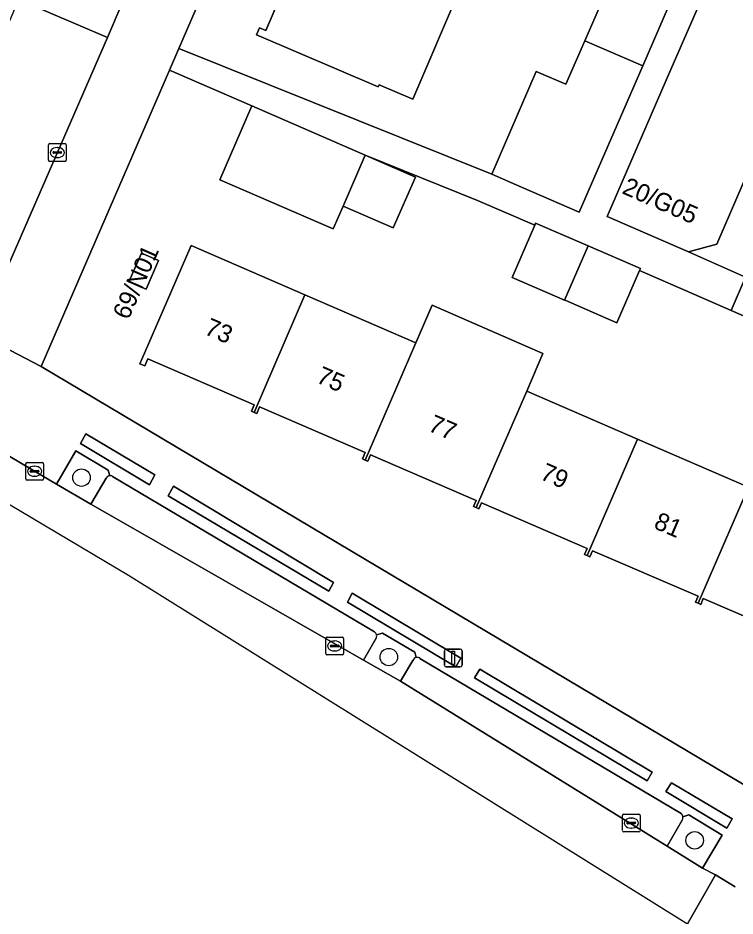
# Model space of a CAD drawing. Extents: x 162803 to 163818, y 381639 to 382475.
# Drawn here: x 163394.5 to 163434.7, y 381804.9 to 381855.2 of the extents above; entities that cross this region are included whole.
import ezdxf

# ---------------------------------------------------------------- set-up
doc = ezdxf.new("R2010")
doc.units = 0
for name, color, linetype in [('IMGEO_Berm_groen', 7, 'Continuous'), ('IMGEO_Boom', 7, 'Continuous'), ('IMGEO_Erf', 7, 'Continuous'), ('IMGEO_Groenvoorziening', 7, 'Continuous'), ('IMGEO_Kolk', 7, 'Continuous'), ('IMGEO_Lichtmast', 7, 'Continuous'), ('IMGEO_Pand', 7, 'Continuous'), ('IMGEO_Pand_nummerreeks', 7, 'Continuous'), ('IMGEO_Parkeervlak_open', 7, 'Continuous'), ('IMGEO_Rijbaan_lokaal_gesloten', 7, 'Continuous'), ('IMGEO_Rijbaan_lokaal_open', 7, 'Continuous'), ('IMGEO_Voetpad_open', 7, 'Continuous')]:
    doc.layers.add(name, color=color, linetype=linetype)

msp = doc.modelspace()

# ---------------------------------------------------------------- linework, layer by layer
at = {"layer": 'IMGEO_Berm_groen'}
for points in [[(163399.544, 381854.142), (163394.559, 381856.298), (163394.49, 381856.13), (163392.212, 381850.821), (163391.661, 381850.394), (163389.556, 381850), (163388.971, 381849.512), (163387.609, 381847.192)], [(163389.452, 381839.39), (163392.292, 381837.534), (163399.544, 381854.142)]]:
    msp.add_lwpolyline(points, dxfattribs=at)
at = {"layer": 'IMGEO_Boom'}
for centre in [(163398.089, 381829.482), (163415.32, 381819.425), (163432.47, 381809.155)]:
    msp.add_circle(centre, 0.489, dxfattribs=at)
at = {"layer": 'IMGEO_Erf'}
for points in [[(163433.958, 381923.664), (163403.547, 381853.528), (163421.091, 381846.477), (163423.59, 381852.241), (163425.254, 381851.519), (163426.307, 381853.949), (163428.657, 381859.374)], [(163419.342, 381856.95), (163416.671, 381850.68), (163414.775, 381851.488), (163414.731, 381851.385), (163407.904, 381854.294), (163408.07, 381854.678), (163408.419, 381854.527), (163410.948, 381860.393)], [(163436.198, 381838.123), (163434.517, 381838.854), (163432.723, 381839.632), (163429.378, 381841.081), (163428.109, 381838.155), (163425.245, 381839.398), (163425.173, 381839.429), (163422.236, 381840.702), (163423.504, 381843.626), (163420.299, 381845.015), (163413.989, 381847.548), (163416.807, 381846.326), (163415.568, 381843.47), (163412.751, 381844.692), (163412.199, 381843.419), (163405.84, 381846.176), (163407.63, 381850.305), (163403.019, 381852.311), (163395.819, 381835.705), (163436.629, 381811.45)], [(163438.975, 381820.104), (163432.952, 381822.703), (163432.812, 381822.379), (163432.665, 381822.443), (163432.518, 381822.507), (163432.658, 381822.83), (163426.732, 381825.387), (163426.587, 381825.052), (163426.44, 381825.116), (163426.293, 381825.18), (163426.438, 381825.514), (163420.511, 381828.071), (163420.368, 381827.74), (163420.221, 381827.804), (163420.074, 381827.868), (163420.217, 381828.198), (163414.29, 381830.755), (163414.137, 381830.401), (163413.99, 381830.465), (163413.843, 381830.529), (163413.996, 381830.882), (163408.07, 381833.439), (163407.912, 381833.075), (163407.765, 381833.138), (163407.618, 381833.201), (163407.776, 381833.566), (163401.81, 381836.14), (163401.638, 381835.742), (163401.368, 381835.859), (163401.495, 381836.153), (163402.857, 381839.295), (163404.241, 381842.487), (163410.618, 381839.723), (163416.834, 381837.028), (163417.748, 381839.137), (163423.964, 381836.441), (163423.05, 381834.333), (163429.266, 381831.638), (163435.482, 381828.943)]]:
    msp.add_lwpolyline(points, dxfattribs=at)
msp.add_lwpolyline([(163401.711, 381840.043), (163400.747, 381840.461), (163401.443, 381842.066), (163402.407, 381841.648)], close=True, dxfattribs=at)
at = {"layer": 'IMGEO_Groenvoorziening'}
for points in [[(163435.32, 381840.713), (163434.517, 381838.854), (163436.198, 381838.123), (163436.268, 381838.286), (163439.015, 381837.095), (163441.782, 381835.896), (163441.712, 381835.735), (163448.992, 381832.592), (163449.775, 381834.399), (163449.934, 381834.765), (163435.46, 381841.037)], [(163398.324, 381831.926), (163398.029, 381831.389), (163401.897, 381829.068), (163402.208, 381829.635)], [(163403.238, 381828.994), (163402.941, 381828.464), (163411.956, 381823.122), (163412.22, 381823.608)], [(163413.257, 381823.001), (163412.996, 381822.5), (163419.074, 381818.874), (163419.357, 381819.373)], [(163420.415, 381818.757), (163420.12, 381818.266), (163429.799, 381812.496), (163430.078, 381812.97)], [(163431.168, 381812.385), (163430.856, 381811.886), (163434.272, 381809.838), (163434.575, 381810.357)]]:
    msp.add_lwpolyline(points, close=True, dxfattribs=at)
for points in [[(163399.682, 381829.584), (163399.575, 381829.895), (163397.779, 381830.986), (163396.691, 381829.107)], [(163396.691, 381829.107), (163398.609, 381827.994), (163399.48, 381829.459)], [(163414.615, 381820.483), (163413.902, 381819.257), (163415.975, 381818.069), (163416.665, 381819.235)], [(163416.86, 381819.395), (163416.785, 381819.695), (163414.959, 381820.767), (163414.634, 381820.669)], [(163431.763, 381810.278), (163430.921, 381808.822), (163432.917, 381807.601), (163434.015, 381809.443), (163432.139, 381810.578), (163431.812, 381810.474)]]:
    msp.add_lwpolyline(points, dxfattribs=at)
for centre, radius, start, end in [((163399.696, 381829.335), 0.249, 93.3052, 150.1942), ((163414.332, 381820.606), 0.308, 336.5018, 11.8331), ((163416.908, 381819.137), 0.262, 100.6135, 158.1252), ((163431.538, 381810.438), 0.276, 324.4834, 7.4441)]:
    msp.add_arc(centre, radius, start, end, dxfattribs=at)
at = {"layer": 'IMGEO_Kolk'}
for p, q in [((163396.23, 381847.27), (163396.23, 381848.122)), ((163396.305, 381848.196), (163397.157, 381848.196)), ((163397.231, 381848.122), (163397.231, 381847.27)), ((163396.489, 381847.69), (163396.489, 381847.702)), ((163396.927, 381847.653), (163396.529, 381847.653)), ((163396.532, 381847.739), (163396.93, 381847.739)), ((163396.718, 381847.976), (163396.743, 381847.976)), ((163396.973, 381847.702), (163396.973, 381847.69)), ((163397.157, 381847.196), (163396.305, 381847.196)), ((163396.741, 381847.416), (163396.716, 381847.416)), ((163394.958, 381829.41), (163394.958, 381830.262)), ((163395.033, 381830.336), (163395.885, 381830.336)), ((163395.26, 381829.879), (163395.658, 381829.879)), ((163395.446, 381830.116), (163395.471, 381830.116)), ((163395.959, 381830.262), (163395.959, 381829.41)), ((163395.217, 381829.83), (163395.217, 381829.842)), ((163395.655, 381829.793), (163395.257, 381829.793)), ((163395.469, 381829.556), (163395.444, 381829.556)), ((163395.701, 381829.842), (163395.701, 381829.83)), ((163395.885, 381829.336), (163395.033, 381829.336)), ((163411.785, 381819.621), (163411.785, 381820.473)), ((163411.86, 381820.547), (163412.712, 381820.547)), ((163412.273, 381820.327), (163412.298, 381820.327)), ((163412.786, 381820.473), (163412.786, 381819.621)), ((163412.044, 381820.041), (163412.044, 381820.053)), ((163412.482, 381820.004), (163412.084, 381820.004)), ((163412.087, 381820.09), (163412.485, 381820.09)), ((163412.528, 381820.053), (163412.528, 381820.041)), ((163412.712, 381819.547), (163411.86, 381819.547)), ((163412.296, 381819.767), (163412.271, 381819.767)), ((163428.415, 381809.699), (163428.415, 381810.551)), ((163428.49, 381810.625), (163429.342, 381810.625)), ((163428.903, 381810.405), (163428.928, 381810.405)), ((163429.416, 381810.551), (163429.416, 381809.699)), ((163428.674, 381810.119), (163428.674, 381810.131)), ((163429.112, 381810.082), (163428.714, 381810.082)), ((163428.717, 381810.168), (163429.115, 381810.168)), ((163428.926, 381809.845), (163428.901, 381809.845)), ((163429.158, 381810.131), (163429.158, 381810.119)), ((163429.342, 381809.625), (163428.49, 381809.625))]:
    msp.add_line(p, q, dxfattribs=at)
for points in [[(163396.23, 381847.27), (163396.23, 381848.122)], [(163396.305, 381848.196), (163397.157, 381848.196)], [(163397.231, 381848.122), (163397.231, 381847.27)], [(163397.157, 381847.196), (163396.305, 381847.196)], [(163394.958, 381829.41), (163394.958, 381830.262)], [(163395.033, 381830.336), (163395.885, 381830.336)], [(163395.959, 381830.262), (163395.959, 381829.41)], [(163395.885, 381829.336), (163395.033, 381829.336)], [(163411.785, 381819.621), (163411.785, 381820.473)], [(163411.86, 381820.547), (163412.712, 381820.547)], [(163412.786, 381820.473), (163412.786, 381819.621)], [(163412.712, 381819.547), (163411.86, 381819.547)], [(163428.415, 381809.699), (163428.415, 381810.551)], [(163428.49, 381810.625), (163429.342, 381810.625)], [(163429.416, 381810.551), (163429.416, 381809.699)], [(163429.342, 381809.625), (163428.49, 381809.625)]]:
    msp.add_lwpolyline(points, dxfattribs=at)
for centre, radius, start, end in [((163396.307, 381848.12), 0.0765, 91.552, 178.448), ((163396.307, 381848.12), 0.0765, 91.552, 178.448), ((163397.155, 381848.12), 0.0765, 1.552, 88.448), ((163397.155, 381848.12), 0.0765, 1.552, 88.448), ((163396.529, 381847.699), 0.0403, 85.8775, 175.7526), ((163396.526, 381847.689), 0.0366, 178.938, 274.7102), ((163396.93, 381847.696), 0.043, 264.8664, 352.4533), ((163396.934, 381847.701), 0.0386, 1.7309, 96.639), ((163396.307, 381847.272), 0.0765, 181.552, 268.448), ((163396.307, 381847.272), 0.0765, 181.552, 268.448), ((163397.155, 381847.272), 0.0765, 271.552, 358.448), ((163397.155, 381847.272), 0.0765, 271.552, 358.448), ((163395.035, 381830.26), 0.0765, 91.552, 178.448), ((163395.035, 381830.26), 0.0765, 91.552, 178.448), ((163395.257, 381829.839), 0.0403, 85.8775, 175.7526), ((163395.662, 381829.841), 0.0386, 1.7309, 96.639), ((163395.883, 381830.26), 0.0765, 1.552, 88.448), ((163395.883, 381830.26), 0.0765, 1.552, 88.448), ((163395.035, 381829.412), 0.0765, 181.552, 268.448), ((163395.035, 381829.412), 0.0765, 181.552, 268.448), ((163395.254, 381829.829), 0.0366, 178.938, 274.7102), ((163395.658, 381829.836), 0.043, 264.8664, 352.4533), ((163395.883, 381829.412), 0.0765, 271.552, 358.448), ((163395.883, 381829.412), 0.0765, 271.552, 358.448), ((163411.862, 381820.471), 0.0765, 91.552, 178.448), ((163411.862, 381820.471), 0.0765, 91.552, 178.448), ((163412.71, 381820.471), 0.0765, 1.552, 88.448), ((163412.71, 381820.471), 0.0765, 1.552, 88.448), ((163412.084, 381820.05), 0.0403, 85.8775, 175.7526), ((163412.081, 381820.04), 0.0366, 178.938, 274.7102), ((163412.485, 381820.047), 0.043, 264.8664, 352.4533), ((163412.489, 381820.052), 0.0386, 1.7309, 96.639), ((163411.862, 381819.623), 0.0765, 181.552, 268.448), ((163411.862, 381819.623), 0.0765, 181.552, 268.448), ((163412.71, 381819.623), 0.0765, 271.552, 358.448), ((163412.71, 381819.623), 0.0765, 271.552, 358.448), ((163428.492, 381810.549), 0.0765, 91.552, 178.448), ((163428.492, 381810.549), 0.0765, 91.552, 178.448), ((163429.34, 381810.549), 0.0765, 1.552, 88.448), ((163429.34, 381810.549), 0.0765, 1.552, 88.448), ((163428.714, 381810.128), 0.0403, 85.8775, 175.7526), ((163428.711, 381810.118), 0.0366, 178.938, 274.7102), ((163429.115, 381810.125), 0.043, 264.8664, 352.4533), ((163429.119, 381810.13), 0.0386, 1.7309, 96.639), ((163428.492, 381809.701), 0.0765, 181.552, 268.448), ((163428.492, 381809.701), 0.0765, 181.552, 268.448), ((163429.34, 381809.701), 0.0765, 271.552, 358.448), ((163429.34, 381809.701), 0.0765, 271.552, 358.448)]:
    msp.add_arc(centre, radius, start, end, dxfattribs=at)
for centre, major_axis, ratio, start_param, end_param in [((163396.717, 381847.696), (-0.387, 0.002), 0.722429, 4.712389, 7.853982), ((163396.742, 381847.696), (-0.39, 0.002), 0.717154, 1.570796, 4.712389), ((163395.445, 381829.836), (-0.387, 0.002), 0.722429, 4.712389, 7.853982), ((163395.47, 381829.836), (-0.39, 0.002), 0.717154, 1.570796, 4.712389), ((163412.272, 381820.047), (-0.387, 0.002), 0.722429, 4.712389, 7.853982), ((163412.297, 381820.047), (-0.39, 0.002), 0.717154, 1.570796, 4.712389), ((163428.902, 381810.125), (-0.387, 0.002), 0.722429, 4.712389, 7.853982), ((163428.927, 381810.125), (-0.39, 0.002), 0.717154, 1.570796, 4.712389)]:
    msp.add_ellipse(centre, major_axis=major_axis, ratio=ratio, start_param=start_param, end_param=end_param, dxfattribs=at)
at = {"layer": 'IMGEO_Lichtmast'}
for p, q in [((163418.537, 381819.876), (163419.327, 381819.876)), ((163419.327, 381819.876), (163418.537, 381819.876)), ((163418.437, 381818.976), (163418.437, 381819.776)), ((163418.437, 381819.776), (163418.437, 381818.976)), ((163419.427, 381819.776), (163419.427, 381818.976)), ((163419.427, 381818.976), (163419.427, 381819.776)), ((163419.327, 381818.876), (163418.537, 381818.876)), ((163418.537, 381818.876), (163419.327, 381818.876))]:
    msp.add_line(p, q, dxfattribs=at)
msp.add_lwpolyline([(163418.857, 381819.751), (163419.007, 381819.751), (163419.007, 381819.001), (163418.857, 381819.001), (163418.857, 381819.751)], dxfattribs=at)
for centre, start, end in [((163418.537, 381819.776), 90, 180), ((163418.537, 381819.776), 90, 180), ((163419.327, 381819.776), 0, 90), ((163419.327, 381819.776), 360, 90), ((163418.537, 381818.976), 180, 270), ((163418.537, 381818.976), 180, 270), ((163419.327, 381818.976), 270, 0), ((163419.327, 381818.976), 270, 0)]:
    msp.add_arc(centre, 0.1, start, end, dxfattribs=at)
at = {"layer": 'IMGEO_Pand'}
for points in [[(163419.342, 381856.95), (163410.697, 381860.675), (163410.634, 381860.528), (163410.948, 381860.393), (163408.419, 381854.527), (163408.07, 381854.678), (163407.904, 381854.294), (163414.731, 381851.385), (163414.775, 381851.488), (163416.671, 381850.68)], [(163431.903, 381857.968), (163431.665, 381858.071), (163428.657, 381859.374), (163426.307, 381853.949), (163429.555, 381852.549)], [(163438.987, 381854.752), (163436.121, 381855.995), (163433.255, 381857.237), (163430.874, 381851.744), (163427.569, 381844.119), (163432.128, 381842.14), (163433.704, 381842.563), (163436.605, 381849.259)], [(163429.555, 381852.549), (163426.307, 381853.949), (163425.254, 381851.519), (163423.59, 381852.241), (163421.091, 381846.477), (163422.756, 381845.755), (163426.001, 381844.348)], [(163413.989, 381847.548), (163407.63, 381850.305), (163405.84, 381846.176), (163412.199, 381843.419), (163412.751, 381844.692)], [(163413.989, 381847.548), (163412.751, 381844.692), (163415.568, 381843.47), (163416.807, 381846.326)], [(163426.491, 381842.468), (163423.554, 381843.742), (163423.504, 381843.626), (163422.236, 381840.702), (163425.173, 381839.429)], [(163410.618, 381839.723), (163404.241, 381842.487), (163402.857, 381839.295), (163401.495, 381836.153), (163401.368, 381835.859), (163401.638, 381835.742), (163401.81, 381836.14), (163407.776, 381833.566), (163407.618, 381833.201), (163407.765, 381833.138)], [(163429.378, 381841.081), (163429.427, 381841.195), (163426.491, 381842.468), (163425.173, 381839.429), (163425.245, 381839.398), (163428.109, 381838.155)], [(163401.711, 381840.043), (163402.407, 381841.648), (163401.443, 381842.066), (163400.747, 381840.461)], [(163416.834, 381837.028), (163410.618, 381839.723), (163407.765, 381833.138), (163407.912, 381833.075), (163408.07, 381833.439), (163413.996, 381830.882), (163413.843, 381830.529), (163413.99, 381830.465)], [(163423.05, 381834.333), (163423.964, 381836.441), (163417.748, 381839.137), (163416.834, 381837.028), (163413.99, 381830.465), (163414.137, 381830.401), (163414.29, 381830.755), (163420.217, 381828.198), (163420.074, 381827.868), (163420.221, 381827.804)], [(163429.266, 381831.638), (163423.05, 381834.333), (163420.221, 381827.804), (163420.368, 381827.74), (163420.511, 381828.071), (163426.438, 381825.514), (163426.293, 381825.18), (163426.44, 381825.116)], [(163435.482, 381828.943), (163429.266, 381831.638), (163426.44, 381825.116), (163426.587, 381825.052), (163426.732, 381825.387), (163432.658, 381822.83), (163432.518, 381822.507), (163432.665, 381822.443)], [(163441.861, 381826.178), (163443.06, 381828.944), (163436.691, 381831.651), (163435.482, 381828.943), (163432.665, 381822.443), (163432.812, 381822.379), (163432.952, 381822.703), (163438.975, 381820.104), (163438.82, 381819.745), (163439.032, 381819.653)]]:
    msp.add_lwpolyline(points, close=True, dxfattribs=at)
at = {"layer": 'IMGEO_Parkeervlak_open'}
for points in [[(163399.48, 381829.459), (163398.609, 381827.994), (163413.902, 381819.257), (163414.615, 381820.483)], [(163414.526, 381820.845), (163399.834, 381829.543)], [(163431.71, 381810.654), (163417.068, 381819.348)], [(163416.665, 381819.235), (163415.975, 381818.069), (163430.921, 381808.822), (163431.763, 381810.278)]]:
    msp.add_lwpolyline(points, dxfattribs=at)
for centre, radius, start, end in [((163399.696, 381829.335), 0.249, 93.3052, 150.1942), ((163399.697, 381829.337), 0.248, 56.3613, 93.4477), ((163414.328, 381820.602), 0.313, 12.3034, 50.7662), ((163414.332, 381820.606), 0.308, 336.5018, 11.8331), ((163416.908, 381819.137), 0.262, 100.6135, 158.1252), ((163416.91, 381819.131), 0.269, 53.8744, 100.66), ((163431.544, 381810.441), 0.27, 7.0239, 52.0537), ((163431.538, 381810.438), 0.276, 324.4834, 7.4441)]:
    msp.add_arc(centre, radius, start, end, dxfattribs=at)
at = {"layer": 'IMGEO_Rijbaan_lokaal_gesloten'}
msp.add_lwpolyline([(163434.734, 381806.559), (163433.645, 381807.215), (163432.06, 381804.479), (163441.867, 381798.366), (163449.899, 381794.075)], dxfattribs=at)
at = {"layer": 'IMGEO_Rijbaan_lokaal_open'}
for points in [[(163454.325, 381847.435), (163450.186, 381849.176), (163448.068, 381844.29), (163445.202, 381845.532), (163442.337, 381846.775), (163439.471, 381848.017), (163436.605, 381849.259), (163433.704, 381842.563), (163432.128, 381842.14), (163435.32, 381840.713), (163435.46, 381841.037), (163449.934, 381834.765), (163451.209, 381837.708), (163450.286, 381838.112)], [(163432.06, 381804.479), (163433.645, 381807.215), (163432.917, 381807.601), (163430.921, 381808.822), (163415.975, 381818.069), (163413.902, 381819.257), (163398.609, 381827.994), (163396.691, 381829.107), (163395.459, 381829.836), (163392.489, 381831.604), (163391.302, 381829.601), (163400.716, 381824.015)]]:
    msp.add_lwpolyline(points, close=True, dxfattribs=at)
at = {"layer": 'IMGEO_Voetpad_open'}
for points in [[(163433.958, 381923.664), (163434.604, 381925.154), (163442.096, 381942.431), (163438.452, 381944.062), (163430.782, 381926.338), (163430.297, 381925.219), (163422.983, 381908.314), (163422.504, 381907.226), (163416.497, 381893.39), (163415.281, 381890.601), (163414.692, 381889.232), (163409.552, 381877.287), (163409.054, 381876.142), (163400.375, 381856.069), (163399.544, 381854.142), (163392.292, 381837.534), (163395.819, 381835.705), (163403.019, 381852.311), (163403.547, 381853.528)], [(163398.324, 381831.926), (163402.208, 381829.635), (163401.897, 381829.068), (163398.029, 381831.389)], [(163403.238, 381828.994), (163412.22, 381823.608), (163411.956, 381823.122), (163402.941, 381828.464)], [(163413.257, 381823.001), (163419.357, 381819.373), (163419.074, 381818.874), (163412.996, 381822.5)], [(163420.415, 381818.757), (163430.078, 381812.97), (163429.799, 381812.496), (163420.12, 381818.266)], [(163431.168, 381812.385), (163434.575, 381810.357), (163434.272, 381809.838), (163430.856, 381811.886)]]:
    msp.add_lwpolyline(points, close=True, dxfattribs=at)
for points in [[(163431.903, 381857.968), (163429.555, 381852.549), (163426.001, 381844.348), (163422.756, 381845.755), (163421.091, 381846.477), (163403.547, 381853.528), (163403.019, 381852.311), (163407.63, 381850.305), (163413.989, 381847.548), (163420.299, 381845.015), (163423.504, 381843.626), (163423.554, 381843.742), (163426.491, 381842.468), (163429.427, 381841.195), (163429.378, 381841.081), (163432.723, 381839.632), (163434.517, 381838.854), (163435.32, 381840.713), (163432.128, 381842.14), (163427.569, 381844.119), (163430.874, 381851.744), (163433.255, 381857.237)], [(163394.559, 381856.298), (163399.544, 381854.142), (163400.375, 381856.069)], [(163436.629, 381811.45), (163395.819, 381835.705), (163392.292, 381837.534), (163389.72, 381833.25), (163392.489, 381831.604), (163395.459, 381829.836), (163396.691, 381829.107), (163397.779, 381830.986), (163399.575, 381829.895), (163399.682, 381829.584)], [(163399.834, 381829.543), (163414.526, 381820.845)], [(163414.634, 381820.669), (163414.959, 381820.767), (163416.785, 381819.695), (163416.86, 381819.395)], [(163417.068, 381819.348), (163431.71, 381810.654)], [(163431.812, 381810.474), (163432.139, 381810.578), (163434.015, 381809.443), (163432.917, 381807.601), (163433.645, 381807.215), (163434.734, 381806.559)]]:
    msp.add_lwpolyline(points, dxfattribs=at)
for centre, radius, start, end in [((163399.697, 381829.337), 0.248, 56.3613, 93.4477), ((163414.328, 381820.602), 0.313, 12.3034, 50.7662), ((163416.91, 381819.131), 0.269, 53.8744, 100.66), ((163431.544, 381810.441), 0.27, 7.0239, 52.0537)]:
    msp.add_arc(centre, radius, start, end, dxfattribs=at)

# ---------------------------------------------------------------- texts
at = {"layer": 'IMGEO_Pand_nummerreeks'}
for s, rotation, p in [('20/G05', 336.3368, (163428.342, 381845.429)), ('69/N01', 66.1726, (163400.716, 381838.274)), ('73', 336.6577, (163404.918, 381837.544)), ('75', 336.6577, (163411.192, 381834.836)), ('77', 336.6577, (163417.467, 381832.129)), ('79', 336.6577, (163423.741, 381829.421)), ('81', 336.6577, (163430.119, 381826.669))]:
    msp.add_text(s, height=1, rotation=rotation, dxfattribs=at).set_placement(p)

doc.saveas('drawing.dxf')
